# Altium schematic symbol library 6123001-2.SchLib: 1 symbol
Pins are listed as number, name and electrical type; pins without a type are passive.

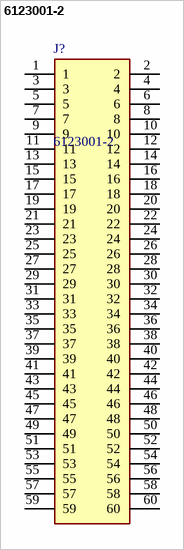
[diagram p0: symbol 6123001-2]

## 6123001-2
designator J?
Board to Board & Mezzanine Connectors 0.8FH P08H.5 060 30/Sn TR SC; Manufacturer_Name: TE Connectivity; Geometry.Height: 7.8mm
footprint 61230012
pins: 1, 2, 3, 4, 5, 6, 7, 8, 9, 10, 11, 12, 13, 14, 15, 16, 17, 18, 19, 20, 21, 22, 23, 24, 25, 26, 27, 28, 29, 30, 31, 32, 33, 34, 35, 36, 37, 38, 39, 40, 41, 42, 43, 44, 45, 46, 47, 48, 49, 50, 51, 52, 53, 54, 55, 56, 57, 58, 59, 60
